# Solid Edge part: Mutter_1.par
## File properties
Sűrűség: 0,000 kg/m^3
Pontosság: 0,990
Author: ahadarics
Last saved by: ahadarics
Revision: 77
Username: ahadarics
Dokumentum tartalom típus: 0
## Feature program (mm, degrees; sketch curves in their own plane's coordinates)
base feature "unnamed BaseFeature 1"
sketch for "unnamed Hole 1" plane through (4, 0, 0) normal (1, 0, 0) x-axis (0, -1, 0)
  hole centre (0, 0) bore radius 2.4585
hole "unnamed Hole 1" through
chamfer "Letörés_1" setback 0.3  SetBackValue2 = 60 deg
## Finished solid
Body 1: solid body, 23 faces, 46 edges, 24 vertices.
  Faces by surface: cone 14, plane 8, cylinder 1
  Edges by curve: spline 24, circle 16, line 6
Bounding box of the edges (mm): 4.000 x 11.547 x 10.000, from (0, -5.7735, -5) to (4, 5.7735, 5).
Cylindrical faces by radius (mm): R2.4585 x1
Conical faces (half-angle, radius in mm at the cone's reference point): 60 deg R2.4585 x1, 60 deg R2.9781 x1, 60 deg R5.3868 x12
Planar faces by outward normal: +x 1, +z 1, -x 1, -z 1, oblique 4
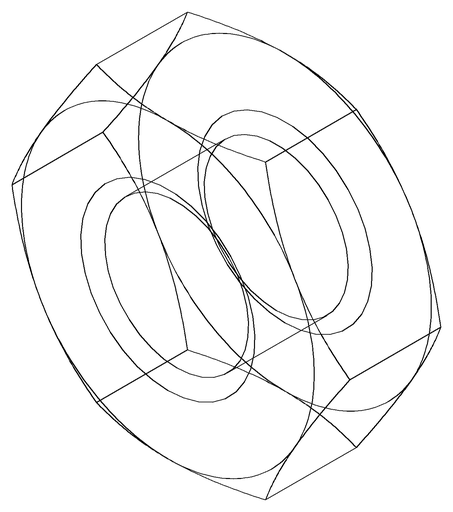
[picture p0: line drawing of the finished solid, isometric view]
